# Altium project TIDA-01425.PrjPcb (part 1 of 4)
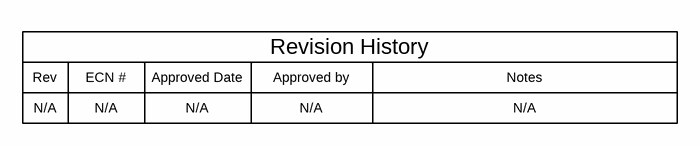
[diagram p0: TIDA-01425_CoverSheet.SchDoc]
TID: TIDA-01425; TechSupport: http://www.ti.com/support; SCH_Rev: E1; PRJ_Title: Stand-Alone Gateway with Ethernet and CAN; PRJ_Number: TIDA-01425; PRJ_Engineer2: Donovan Porter; PRJ_Engineer: Heather Lothamer; PRJ_Customer: Public Release; PCB_Rev: E1; PCB_Layout: Krypton; CopyrightYear: 2017
12 sheets, 496 parts. Net scope: global (net labels, ports and power ports of the same name join across sheets).
Board file: TIDA-01425.PcbDoc
Sheets:
  TIDA-01425_CoverSheet.SchDoc
  DCDC PWR.schdoc
  LP873x (PMIC).SchDoc
  ANA PWR.SchDoc
  DIG PWR.SchDoc
  J6Entry.SchDoc
  J6E DDR.SchDoc
  DDR3.schdoc
  Ethernet_subsystem.SchDoc
  CAN_subsystem2.0.SchDoc
  JTAG.SchDoc
  TIDA-01425_EVM_Hardware.SchDoc

## Sheet TIDA-01425_CoverSheet.SchDoc: CoverSheet
size 431 x 279 mm; Date: Not shown in title block; ApprovedBy: Not shown in title block; CheckedBy: Not shown in title block; Author: Not shown in title block; CompanyName: Not shown in title block; DrawnBy: Donovan Porter; Engineer: Not shown in title block; Organization: Not shown in title block; Address1: Not shown in title block; Address2: Not shown in title block; Address3: Not shown in title block; Address4: Not shown in title block; DocumentNumber: 1; Revision: Use project parameter SCH_Rev; SheetNumber: 1; SheetTotal: 12; PageSetup: Record=PageOptions¦CenterHorizontal=True¦CenterVertical=True¦PrintScale=1.00¦XCorrection=1.00¦YCorrection=1.00¦PrintKind=0¦BorderSize=5000000¦LeftOffset=0¦BottomOffset=0¦Orientation=2¦PaperLength=1000¦PaperWidth=1000¦Scale=100¦PaperSource=15¦PrintQuality=600¦MediaType=1¦DitherType=10¦PaperKind=Letter¦PrintScaleMode=1

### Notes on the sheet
- Rev
- N/A
- ECN #
- Approved Date
- Approved by
- Revision History
- Notes

## Sheet DCDC PWR.schdoc: LM53635-Q1
size 431 x 279 mm; Date: Not shown in title block; ApprovedBy: Not shown in title block; CheckedBy: Not shown in title block; Author: Not shown in title block; CompanyName: Not shown in title block; DrawnBy: Donovan Porter; Engineer: Not shown in title block; Organization: Not shown in title block; Address1: Not shown in title block; Address2: Not shown in title block; Address3: Not shown in title block; Address4: Not shown in title block; DocumentNumber: 7; Revision: Use project parameter SCH_Rev; SheetNumber: 7; SheetTotal: 12; PageSetup: Record=PageOptions¦CenterHorizontal=True¦CenterVertical=True¦PrintScale=1.00¦XCorrection=1.00¦YCorrection=1.00¦PrintKind=0¦BorderSize=5000000¦LeftOffset=0¦BottomOffset=0¦Orientation=2¦PaperLength=1000¦PaperWidth=1000¦Scale=100¦PaperSource=15¦PrintQuality=600¦MediaType=1¦DitherType=10¦PaperKind=Letter¦PrintScaleMode=1
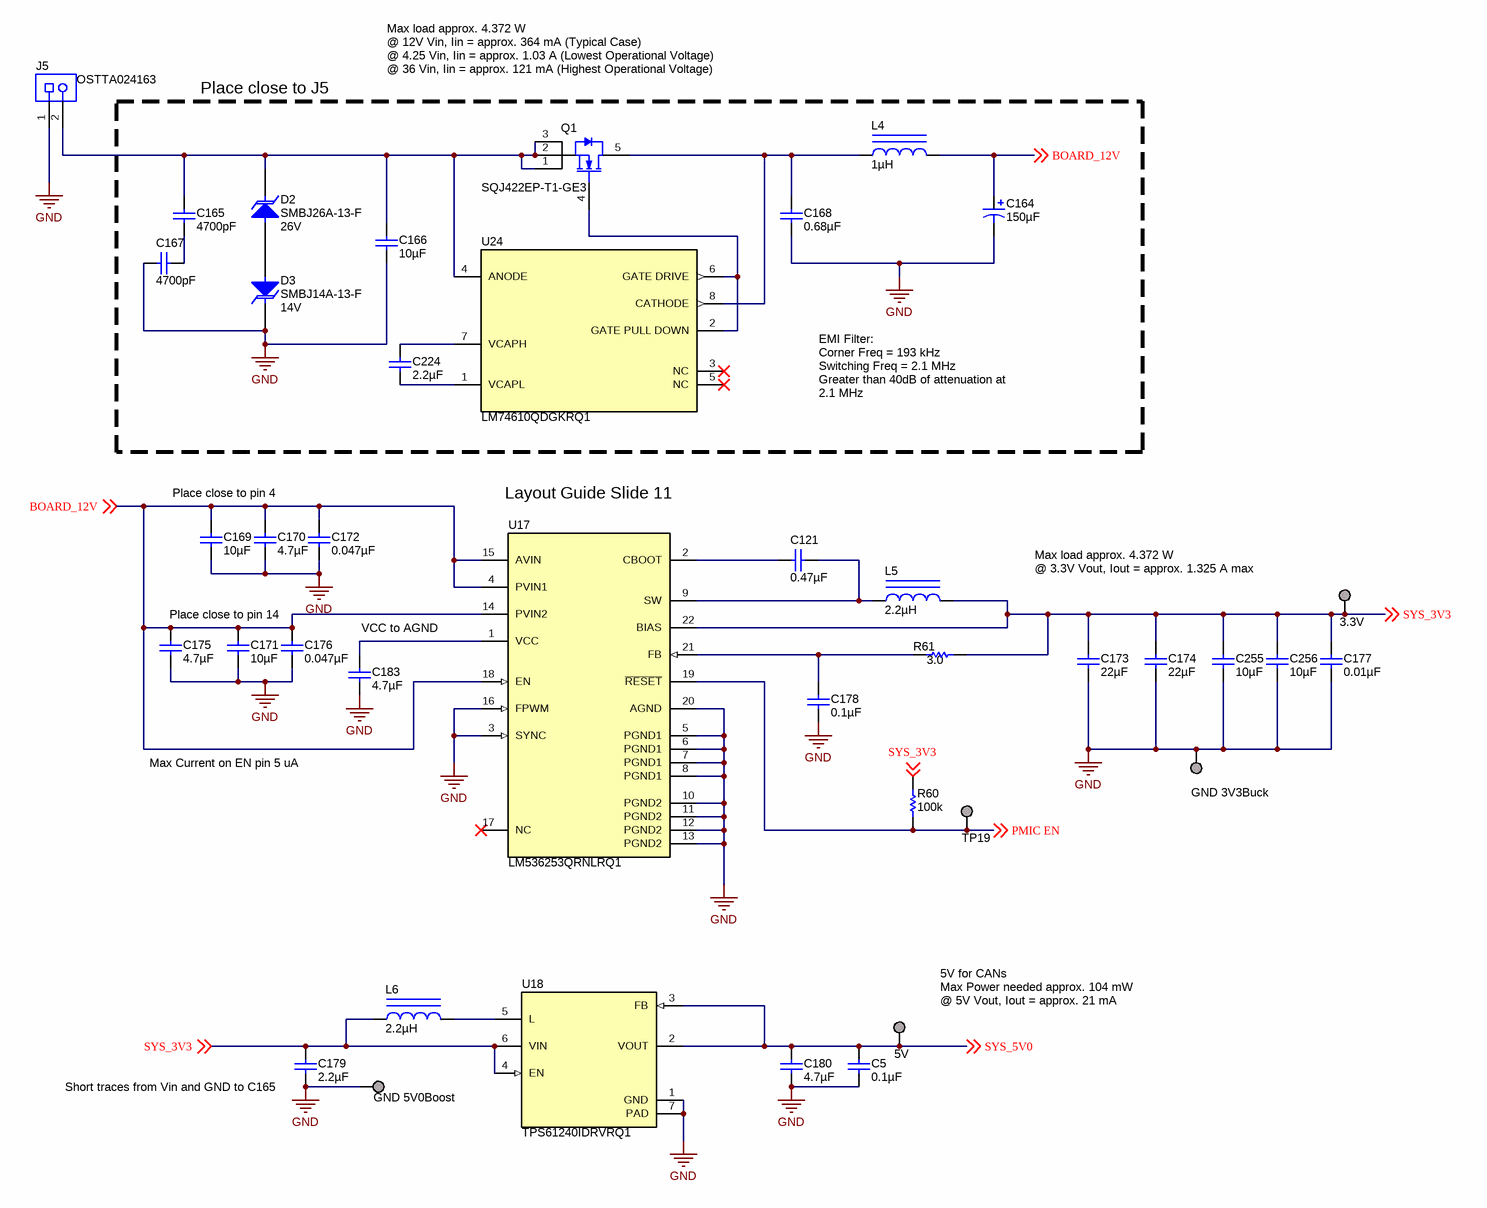
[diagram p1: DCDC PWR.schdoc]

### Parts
3.3V  PAD_1MM_SQUARE  [PAD_1MM_SQUARE]  (value not drawn)  (no BOM)
5V  PAD_1MM_SQUARE  [PAD_1MM_SQUARE]  (value not drawn)  (no BOM)
C5  ValueDisplayed: 0.1µF  [0402]  (hidden comment: GRM155R71C104JA88D)
C121  ValueDisplayed: 0.47µF  [0402]  (hidden comment: JMK105B7474KVHF)
C164  ValueDisplayed: 150µF  [SM_RADIAL_10BMM]  (hidden comment: UUD1H151MNL1GS)
C165  ValueDisplayed: 4700pF  [0402]  (hidden comment: GRM155R71H472KA01D)
C166  ValueDisplayed: 10µF  [1210_270]  (hidden comment: GRM32ER71H106KA12L)
C167  ValueDisplayed: 4700pF  [0402]  (hidden comment: GRM155R71H472KA01D)
C168  ValueDisplayed: 0.68µF  [1210_150]  (hidden comment: GRM32NR71H684KA01L)
C169  ValueDisplayed: 10µF  [1206_180]  (hidden comment: CL31B106KBHNNNE)
C170  ValueDisplayed: 4.7µF  [1206_180]  (hidden comment: C3216X7R1H475K160AC)
C171  ValueDisplayed: 10µF  [1206_180]  (hidden comment: CL31B106KBHNNNE)
C172  ValueDisplayed: 0.047µF  [0805_HV]  (hidden comment: GRM21BR71H473KA01L)
C173  ValueDisplayed: 22µF  [1210_280]  (hidden comment: C3225X7R1C226K250AC)
C174  ValueDisplayed: 22µF  [1210_280]  (hidden comment: C3225X7R1C226K250AC)
C175  ValueDisplayed: 4.7µF  [1206_180]  (hidden comment: C3216X7R1H475K160AC)
C176  ValueDisplayed: 0.047µF  [0805_HV]  (hidden comment: GRM21BR71H473KA01L)
C177  ValueDisplayed: 0.01µF  [0402_065]  (hidden comment: 520L103KT16T)
C178  ValueDisplayed: 0.1µF  [0603]  (hidden comment: C1608X7R1E104K080AA)
C179  ValueDisplayed: 2.2µF  [0603]  (hidden comment: CGA3E1X7S1C225M080AC)
C180  ValueDisplayed: 4.7µF  [1206_180]  (hidden comment: GCM31CR71C475KA37L)
C183  ValueDisplayed: 4.7µF  [1210_280]  (hidden comment: 1210ZC475KAT2A)
C224  ValueDisplayed: 2.2µF  [0805_HV]  (hidden comment: GRM21BR71C225KA12L)
C255  ValueDisplayed: 10µF  [0805_HV]  (hidden comment: EMK212BB7106MG-T)
C256  ValueDisplayed: 10µF  [0805_HV]  (hidden comment: EMK212BB7106MG-T)
D2  SMBJ26A-13-F  value 26V  [SMB]
D3  SMBJ14A-13-F  value 14V  [SMB]
GND_3V3Buck  PAD_3.2x1.9MM_SMD  [PAD_3-2x1-9MM_SMD]  (value not drawn)  (no BOM)
GND_5V0Boost  PAD_3.2x1.9MM_SMD  [PAD_3-2x1-9MM_SMD]  (value not drawn)  (no BOM)
J5  OSTTA024163  [On-Shore_OSTTA024163]
L4  ValueDisplayed: 1µH  [SRN4012TA]  (hidden comment: SRN4012TA-1R0M)
L5  ValueDisplayed: 2.2µH  [WE-TPC-XLH2]  (hidden comment: 7440650022)
L6  ValueDisplayed: 2.2µH  [B82462G4]  (hidden comment: B82462G4222M)
Q1  SQJ422EP-T1-GE3  [PowerPAK_SO-8L]
R60  ValueDisplayed: 100k  [0805_HV]  (hidden comment: RR1220P-104-D)
R61  ValueDisplayed: 3.0  [0603]  (hidden comment: CRCW06033R00JNEA)
TP19  PAD_1MM_SQUARE  [PAD_1MM_SQUARE]  (value not drawn)  (no BOM)
U17  LM536253QRNLRQ1  [RNL0022A_NV]
U18  TPS61240IDRVRQ1  [DRV0006A]
U24  LM74610QDGKRQ1  [DGK0008A_N]

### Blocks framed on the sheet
Place close to J5: C164-C168 C224 D2 D3 L4 Q1 U24

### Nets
GND: C5.2 C164.2(-) C166.2 C167.1 C168.2 C169.2 C170.2 C171.2 C172.2 C173.2 C174.2 C175.2 C176.2 C177.2 C178.2 C179.2 C180.2 C183.2 C255.2 C256.2 D3.1(K) GND_3V3Buck.1 GND_5V0Boost.1 J5.1 U17.3(SYNC) U17.5(PGND1) U17.6(PGND1) U17.7(PGND1) U17.8(PGND1) U17.10(PGND2) U17.11(PGND2) U17.12(PGND2) U17.13(PGND2) U17.16(FPWM) U17.20(AGND) U18.1(GND) U18.7(PAD)
BOARD_12V: C164.1(+) C169.1 C170.1 C171.1 C172.1 C175.1 C176.1 L4.2 U17.4(PVIN1) U17.14(PVIN2) U17.15(AVIN) U17.18(EN) ; off-sheet BOARD_12V
PMIC EN: R60.1 TP19.1 U17.19(~{RESET}) ; off-sheet PMIC EN
SYS_3V3: 3.3V.1 C173.1 C174.1 C177.1 C179.1 C255.1 C256.1 L5.2 L6.1 R60.2 R61.2 U17.22(BIAS) U18.4(EN) U18.6(VIN) ; off-sheet SYS_3V3
SYS_5V0: 5V.1 C5.1 C180.1 U18.2(VOUT) U18.3(FB) ; off-sheet SYS_5V0
NetC121_1: C121.1 L5.1 U17.9(SW)
NetC121_2: C121.2 U17.2(CBOOT)
NetC165_1: C165.1 C166.1 D2.1(K) J5.2 Q1.1(S) Q1.2(S) Q1.3(S) U24.4(ANODE)
NetC165_2: C165.2 C167.2
NetC168_1: C168.1 L4.1 Q1.5(D) U24.8(CATHODE)
NetC178_1: C178.1 R61.1 U17.21(FB)
NetC183_1: C183.1 U17.1(VCC)
NetC224_1: C224.1 U24.7(VCAPH)
NetC224_2: C224.2 U24.1(VCAPL)
NetD2_2: D2.2(A) D3.2(A)
NetL6_2: L6.2 U18.5(L)
NetQ1_4: Q1.4(G) U24.2(GATE_PULL_DOWN) U24.6(GATE_DRIVE)

Not connected (* = marked no-connect by the designer): U17 17(NC)*; U24 3(NC)* 5(NC)*

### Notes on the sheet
- Max load approx. 4.372 W
  @ 12V Vin, Iin = approx. 364 mA (Typical Case)
  @ 4.25 Vin, Iin = approx. 1.03 A (Lowest Operational Voltage)
  @ 36 Vin, Iin = approx. 121 mA (Highest Operational Voltage)
- EMI Filter:
  Corner Freq = 193 kHz
  Switching Freq = 2.1 MHz
  Greater than 40dB of attenuation at 2.1 MHz
- Place close to pin 4
- Layout Guide Slide 11
- (near 3.3V) Max load approx. 4.372 W
  @ 3.3V Vout, Iout = approx. 1.325 A max
- Place close to pin 14
- (near C183) VCC to AGND
- Max Current on EN pin 5 uA
- (near 5V) 5V for CANs
  Max Power needed approx. 104 mW
  @ 5V Vout, Iout = approx. 21 mA
- (near C179) Short traces from Vin and GND to C165

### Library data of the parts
3.3V 5V TP19 = PAD_1MM_SQUARE: 1.0x1.0mm pad, square, SMD; Manufacturer: Any
C5 = GRM155R71C104JA88D: CAP, CERM, 0.1 µF, 16 V, +/- 5%, X7R, 0402; Manufacturer: MuRata; Polarized: N; CompType: Capacitor; Value: 0.1uF; U/M: EA; Cap_F: 0.0000001; Tolerance_%: 5; Value1: Unknown; VDC_V: 16; Value2: 16V; TaMin_C: -55; TaMax_C: 125; SizeArea_mm2: 0.5; SizeAreaWB_mm2: 3; SizeX_mm: 1; SizeZ_mm: 0.6; AEC Category: Q200
C121 = JMK105B7474KVHF: CAP, CERM, 0.47 µF, 6.3 V, +/- 10%, X7R, 0402; Manufacturer: Taiyo Yuden; Polarized: N; CompType: Capacitor; Value: 0.47uF; U/M: EA; Cap_F: 0.00000047; Tolerance_%: 10; Value1: Unknown; VDC_V: 6.3; Value2: 6.3V; TaMin_C: -55; TaMax_C: 125; SizeArea_mm2: 0.5; SizeAreaWB_mm2: 3; SizeX_mm: 1; SizeZ_mm: 0.6; AEC Category: Q200
C164 = UUD1H151MNL1GS: CAP, AL, 150 µF, 50 V, +/- 20%, 0.18 ohm, SMD; Manufacturer: Nichicon; Polarized: Y; CompType: Capacitor; Value: 150uF; U/M: EA; Cap_F: 0.00015; Tolerance_%: 20; VDC_V: 50; Value2: 50V; ESR_ohm: 0.18; IRMS_A: 0.67; TaMin_C: -55; TaMax_C: 105; Cap_Case: 10x10; SizeAreaWB_mm2: 159.9; SizeArea_mm2: 113.3; SizeX_mm: 11; SizeY_mm: 10.3; SizeZ_mm: 10.2; AEC Category: Q200
C165 C167 = GRM155R71H472KA01D: CAP, CERM, 4700 pF, 50 V, +/- 10%, X7R, 0402; Manufacturer: MuRata; Polarized: N; CompType: Capacitor; Value: 4700pF; U/M: EA; Cap_F: 0.0000000047; Tolerance_%: 10; Value1: Unknown; VDC_V: 50; Value2: 50V; TaMin_C: -55; TaMax_C: 125; SizeArea_mm2: 0.5; SizeAreaWB_mm2: 3; SizeX_mm: 1; SizeZ_mm: 0.6; AEC Category: Q200
C166 = GRM32ER71H106KA12L: CAP, CERM, 10 µF, 50 V, +/- 10%, X7R, 1210; Manufacturer: MuRata; Polarized: N; CompType: Capacitor; Value: 10uF; U/M: EA; Cap_F: 0.00001; Tolerance_%: 10; Value1: Unknown; VDC_V: 50; Value2: 50V; TaMin_C: -55; TaMax_C: 125; Cap_Case: 1210; SizeArea_mm2: 8; SizeAreaWB_mm2: 14.7; SizeX_mm: 3.2; SizeY_mm: 2.5; SizeZ_mm: 2.7; AEC Category: Q200
C168 = GRM32NR71H684KA01L: CAP, CERM, 0.68 µF, 50 V, +/- 10%, X7R, 1210; Manufacturer: MuRata; Polarized: N; CompType: Capacitor; Value: 0.68uF; U/M: EA; Cap_F: 0.00000068; Tolerance_%: 10; Value1: Unknown; VDC_V: 50; Value2: 50V; TaMin_C: -55; TaMax_C: 125; Cap_Case: 1210; SizeArea_mm2: 8; SizeAreaWB_mm2: 14.7; SizeX_mm: 3.2; SizeY_mm: 2.5; SizeZ_mm: 1.5; AEC Category: Q200
C169 C171 = CL31B106KBHNNNE: CAP, CERM, 10 µF, 50 V, +/- 10%, X7R, 1206; Manufacturer: Samsung; Polarized: N; CompType: Capacitor; Value: 10uF; U/M: EA; Cap_F: 0.00001; Tolerance_%: 10; Value1: Unknown; VDC_V: 50; Value2: 50V; TaMin_C: -55; TaMax_C: 125; Cap_Case: 1206; SizeArea_mm2: 5.12; SizeAreaWB_mm2: 10.92; SizeX_mm: 3.2; SizeY_mm: 1.6; SizeZ_mm: 1.8; AEC Category: Q200
C170 C175 = C3216X7R1H475K160AC: CAP, CERM, 4.7 µF, 50 V, +/- 10%, X7R, 1206; Manufacturer: TDK; Polarized: N; CompType: Capacitor; Value: 4.7uF; U/M: EA; Cap_F: 0.0000047; Tolerance_%: 10; ESR_ohm: 0.003158; Value1: 0.003158 ohm; VDC_V: 50; Value2: 50V; IRMS_A: 4.08379; TaMin_C: -55; TaMax_C: 125; SizeArea_mm2: 5.12; SizeAreaWB_mm2: 10.92; SizeX_mm: 3.2; SizeY_mm: 1.6; SizeZ_mm: 1.8; AEC Category: Q200
C172 C176 = GRM21BR71H473KA01L: CAP, CERM, 0.047 µF, 50 V, +/- 10%, X7R, 0805; Manufacturer: MuRata; Polarized: N; CompType: Capacitor; Value: 0.047uF; U/M: EA; Cap_F: 0.000000047; Tolerance_%: 10; Value1: Unknown; VDC_V: 50; Value2: 50V; TaMin_C: -55; TaMax_C: 125; Cap_Case: 0805; SizeArea_mm2: 2.5; SizeAreaWB_mm2: 6.75; SizeX_mm: 2; SizeY_mm: 1.25; SizeZ_mm: 1.45; AEC Category: Q200
C173 C174 = C3225X7R1C226K250AC: CAP, CERM, 22 µF, 16 V, +/- 10%, X7R, 1210; Manufacturer: TDK; Polarized: N; CompType: Capacitor; Value: 22uF; U/M: EA; Cap_F: 0.000022; Tolerance_%: 10; ESR_ohm: 0.002582; Value1: 0.002582 ohm; VDC_V: 16; Value2: 16V; IRMS_A: 4.57562; TaMin_C: -55; TaMax_C: 125; SizeArea_mm2: 8; SizeAreaWB_mm2: 14.7; SizeX_mm: 3.2; SizeY_mm: 2.5; SizeZ_mm: 2.8; AEC Category: Q200
C177 = 520L103KT16T: CAP, CERM, 0.01 µF, 16 V, +/- 10%, X7R, 0402; Manufacturer: AT Ceramics; Polarized: N; CompType: Capacitor; Value: 0.01uF; U/M: EA; Cap_F: 0.00000001; Tolerance_%: 10; Value1: Unknown; VDC_V: 16; Value2: 16V; TaMin_C: -55; TaMax_C: 125; Cap_Case: 0402; SizeArea_mm2: 0.5; SizeAreaWB_mm2: 3; SizeX_mm: 1; SizeZ_mm: 0.65; AEC Category: Q200
C178 = C1608X7R1E104K080AA: CAP, CERM, 0.1 µF, 25 V, +/- 10%, X7R, 0603; Manufacturer: TDK; Polarized: N; CompType: Capacitor; Value: 0.1uF; U/M: EA; Cap_F: 0.0000001; Tolerance_%: 10; Value1: Unknown; VDC_V: 25; Value2: 25V; TaMin_C: -55; TaMax_C: 125; SizeArea_mm2: 1.28; SizeAreaWB_mm2: 4.68; SizeX_mm: 1.6; SizeY_mm: 0.8; SizeZ_mm: 1; AEC Category: Q200
C179 = CGA3E1X7S1C225M080AC: CAP, CERM, 2.2 µF, 16 V, +/- 20%, X7S, AEC-Q200 Grade 1, 0603; Manufacturer: TDK; Polarized: N; CompType: Capacitor; Value: 2.2uF; U/M: EA; Cap_F: 0.0000022; Tolerance_%: 20; Value1: Unknown; VDC_V: 16; Value2: 16V; TaMin_C: -55; TaMax_C: 125; SizeArea_mm2: 1.28; SizeAreaWB_mm2: 4.68; SizeX_mm: 1.6; SizeY_mm: 0.8; SizeZ_mm: 1; AEC Category: Q200; AEC Qualified: Y
C180 = GCM31CR71C475KA37L: CAP, CERM, 4.7 µF, 16 V, +/- 10%, X7R, AEC-Q200 Grade 1, 1206; Manufacturer: MuRata; Polarized: N; CompType: Capacitor; Value: 4.7uF; U/M: EA; Cap_F: 0.0000047; Tolerance_%: 10; Value1: Unknown; VDC_V: 16; Value2: 16V; TaMin_C: -55; TaMax_C: 125; Cap_Case: 1206; SizeArea_mm2: 5.12; SizeAreaWB_mm2: 10.92; SizeX_mm: 3.2; SizeY_mm: 1.6; SizeZ_mm: 1.8; AEC Category: Q200; AEC Qualified: Y; AEC Grade: 1
C183 = 1210ZC475KAT2A: CAP, CERM, 4.7 µF, 10 V, +/- 10%, X7R, 1210; Manufacturer: AVX; Polarized: N; CompType: Capacitor; Value: 4.7uF; U/M: EA; Cap_F: 0.0000047; Tolerance_%: 10; Value1: Unknown; Value2: 10V; TaMin_C: -55; TaMax_C: 125; Cap_Case: 1210; SizeArea_mm2: 8; SizeAreaWB_mm2: 14.7; SizeX_mm: 3.2; SizeY_mm: 2.5; SizeZ_mm: 2.8; AEC Category: Q200
C224 = GRM21BR71C225KA12L: CAP, CERM, 2.2 µF, 16 V, +/- 10%, X7R, 0805; Manufacturer: MuRata; Polarized: N; CompType: Capacitor; Value: 2.2uF; U/M: EA; Cap_F: 0.0000022; Tolerance_%: 10; ESR_ohm: 0.004; Value1: 0.004 ohm; VDC_V: 16; Value2: 16V; TaMin_C: -55; TaMax_C: 125; Cap_Case: 0805; SizeArea_mm2: 2.5; SizeAreaWB_mm2: 6.75; SizeX_mm: 2; SizeY_mm: 1.25; SizeZ_mm: 1.45; AEC Category: Q200
C255 C256 = EMK212BB7106MG-T: CAP, CERM, 10 µF, 16 V, +/- 20%, X7R, 0805; Manufacturer: Taiyo Yuden; Polarized: N; CompType: Capacitor; Value: 10uF; U/M: EA; Cap_F: 0.00001; Tolerance_%: 20; Value1: Unknown; VDC_V: 16; Value2: 16V; TaMin_C: -55; TaMax_C: 125; Cap_Case: 0805; SizeArea_mm2: 2.5; SizeAreaWB_mm2: 6.75; SizeX_mm: 2; SizeY_mm: 1.25; SizeZ_mm: 1.45; AEC Category: Q200
D2 = SMBJ26A-13-F: Diode, TVS, Uni, 26 V, 42.1 Vc, SMB; Manufacturer: Diodes Inc.; U/M: EA; Power_W: 5; Vr_V: 26; Value1: 5W; SizeAreaWB_mm2: 44.156; SizeArea_mm2: 21.336; SizeX_mm: 5.6; SizeY_mm: 3.81; SizeZ_mm: 2.6; AEC Category: Q101
D3 = SMBJ14A-13-F: Diode, TVS, Uni, 14 V, 23.2 Vc, SMB; Manufacturer: Diodes Inc.; U/M: EA; Power_W: 5; Vr_V: 14; Value1: 5W; SizeAreaWB_mm2: 44.156; SizeArea_mm2: 21.336; SizeX_mm: 5.6; SizeY_mm: 3.81; SizeZ_mm: 2.6; AEC Category: Q101
GND_3V3Buck GND_5V0Boost = PAD_3.2x1.9MM_SMD: 3.2x1.9mm Pad, SMD; Manufacturer: Any
J5 = OSTTA024163: Terminal Block, 2x1, 5.08mm, TH; Manufacturer: On-Shore Technology; SymbolCreator: a0412235
L4 = SRN4012TA-1R0M: Inductor, Shielded, Ferrite, 1 µH, 2.2 A, 0.0504 ohm, AEC-Q200 Grade 1, SMD; Manufacturer: Bourns; Value: 1uH; Ind_H: 1.0E-6; Imax_A: 2.2; Irms: 2.2A @ 40C rise; Isat: 2.8A @ 30% inductance drop; DCR_ohm: 0.0504; Value2: 2.2A; SizeAreaWB_mm2: 25; SizeArea_mm2: 16; SizeX_mm: 4; SizeZ_mm: 1.2; AEC Category: Q200; AEC Qualified: Y; AEC Grade: 1
L5 = 7440650022: Inductor, Shielded Drum Core, Ferrite, 2.2 µH, 5.9 A, 0.0104 ohm, SMD; Manufacturer: Wurth Elektronik; Value: 2.2uH; Ind_H: 2.2E-6; Imax_A: 5.9; Irms: 6.2A @ 30C rise; Isat: 5.9A @ 35% inductance drop; DCR_ohm: 0.0104; Value2: 5.9A; SizeAreaWB_mm2: 144; SizeArea_mm2: 100; SizeX_mm: 10; SizeZ_mm: 2.8; AEC Category: Q200
L6 = B82462G4222M: Inductor, Shielded Drum Core, Ferrite, 2.2 µH, 2.55 A, 0.025 ohm, AEC-Q200 Grade 0, SMD; Manufacturer: TDK; Value: 2.2uH; Ind_H: 2.2E-6; Imax_A: 2.55; Irms: 2.55A @ 40C rise; Isat: 2.6A @ 10% inductance drop; DCR_ohm: 0.025; Value2: 2.55A; AEC Category: Q200; AEC Qualified: Y; AEC Grade: 0
Q1 = SQJ422EP-T1-GE3: MOSFET, N-CH, 40 V, 75 A, PowerPAK_SO-8L; Manufacturer: Vishay-Siliconix; Alternate Manufacturer: None; SymbolCreator: a0412235; U/M: EA; ChType: N; Value: 40V; VdsMax_V: 40; Value1: 0.0043 ohm; Rdson45_ohm: 0.0043; Value2: 67 nC; QgTyp_nC: 67; Vgs_V: 20; IdsMax_A: 75; SizeAreaWB_mm2: 58.1095; SizeArea_mm2: 31.5495; SizeX_mm: 6.15; SizeY_mm: 5.13; SizeZ_mm: 1.14; AEC Category: Q101
R60 = RR1220P-104-D: RES, 100 k, 0.5%, 0.1 W, 0805; Manufacturer: Susumu Co Ltd; CompType: Resistor; Value: 100k; Res_ohm: 100000; Tolerance_%: 0.5; Power_W: 0.1; Value2: 0.1W; VDC_V: 100; TempCo: 25 ppm/C; SizeArea_mm2: 2.5; SizeX_mm: 2; SizeY_mm: 1.25; SizeZ_mm: 1.45; EIA_Code: E192; U/M: EA; AEC Category: Q200
R61 = CRCW06033R00JNEA: RES, 3.0, 5%, 0.1 W, 0603; Manufacturer: Vishay-Dale; CompType: Resistor; Value: 3.0; Res_ohm: 3; Value_Code: 3R00; Tolerance_%: 5; Power_W: 0.1; Value2: 0.1W; VDC_V: 75; TempCo: 200 ppm/C; EIA_Code: E24; U/M: EA; AEC Category: Q200
U17 = LM536253QRNLRQ1: 2.5/3.5A, 36 V Synchronous, 2.1MHz, Automotive Step Down DC-DC Converter, RNL0022A (VQFN-HR-22); Alternate PartNumber: LM536253QRNLTQ1; Manufacturer: Texas Instruments; SymbolCreator: Altium; SizeArea_mm2: 20; SizeAreaWB_mm2: 42; SizeX_mm: 4; SizeY_mm: 5; SizeZ_mm: 0.9; CompType: IC; U/M: EA
U18 = TPS61240IDRVRQ1: Automotive Catalog 5V, 400mA, 4MHz Step-Up DC/DC Converter, DRV0006A; Manufacturer: Texas Instruments; SymbolCreator: a799628; SizeArea_mm2: 4; SizeAreaWB_mm2: 9; SizeX_mm: 2; SizeZ_mm: 0.8; CompType: IC; U/M: EA
U24 = LM74610QDGKRQ1: Zero Iq Reverse Polarity Protection Smart Diode Controller, DGK0008A (VSSOP-8); Manufacturer: Texas Instruments; SymbolCreator: Altium; SizeArea_mm2: 15.655; SizeAreaWB_mm2: 35.955; SizeX_mm: 5.05; SizeY_mm: 3.1; SizeZ_mm: 1.1; CompType: IC; U/M: EA

## Sheet LP873x (PMIC).SchDoc: PMIC
size 431 x 279 mm; Date: Not shown in title block; ApprovedBy: Not shown in title block; CheckedBy: Not shown in title block; Author: Not shown in title block; CompanyName: Not shown in title block; DrawnBy: Donovan Porter; Engineer: Not shown in title block; Organization: Not shown in title block; Address1: Not shown in title block; Address2: Not shown in title block; Address3: Not shown in title block; Address4: Not shown in title block; DocumentNumber: 2; Revision: Use project parameter SCH_Rev; SheetNumber: 2; SheetTotal: 12; PageSetup: Record=PageOptions¦CenterHorizontal=True¦CenterVertical=True¦PrintScale=1.00¦XCorrection=1.00¦YCorrection=1.00¦PrintKind=0¦BorderSize=5000000¦LeftOffset=0¦BottomOffset=0¦Orientation=2¦PaperLength=1000¦PaperWidth=1000¦Scale=100¦PaperSource=15¦PrintQuality=600¦MediaType=1¦DitherType=10¦PaperKind=Letter¦PrintScaleMode=1
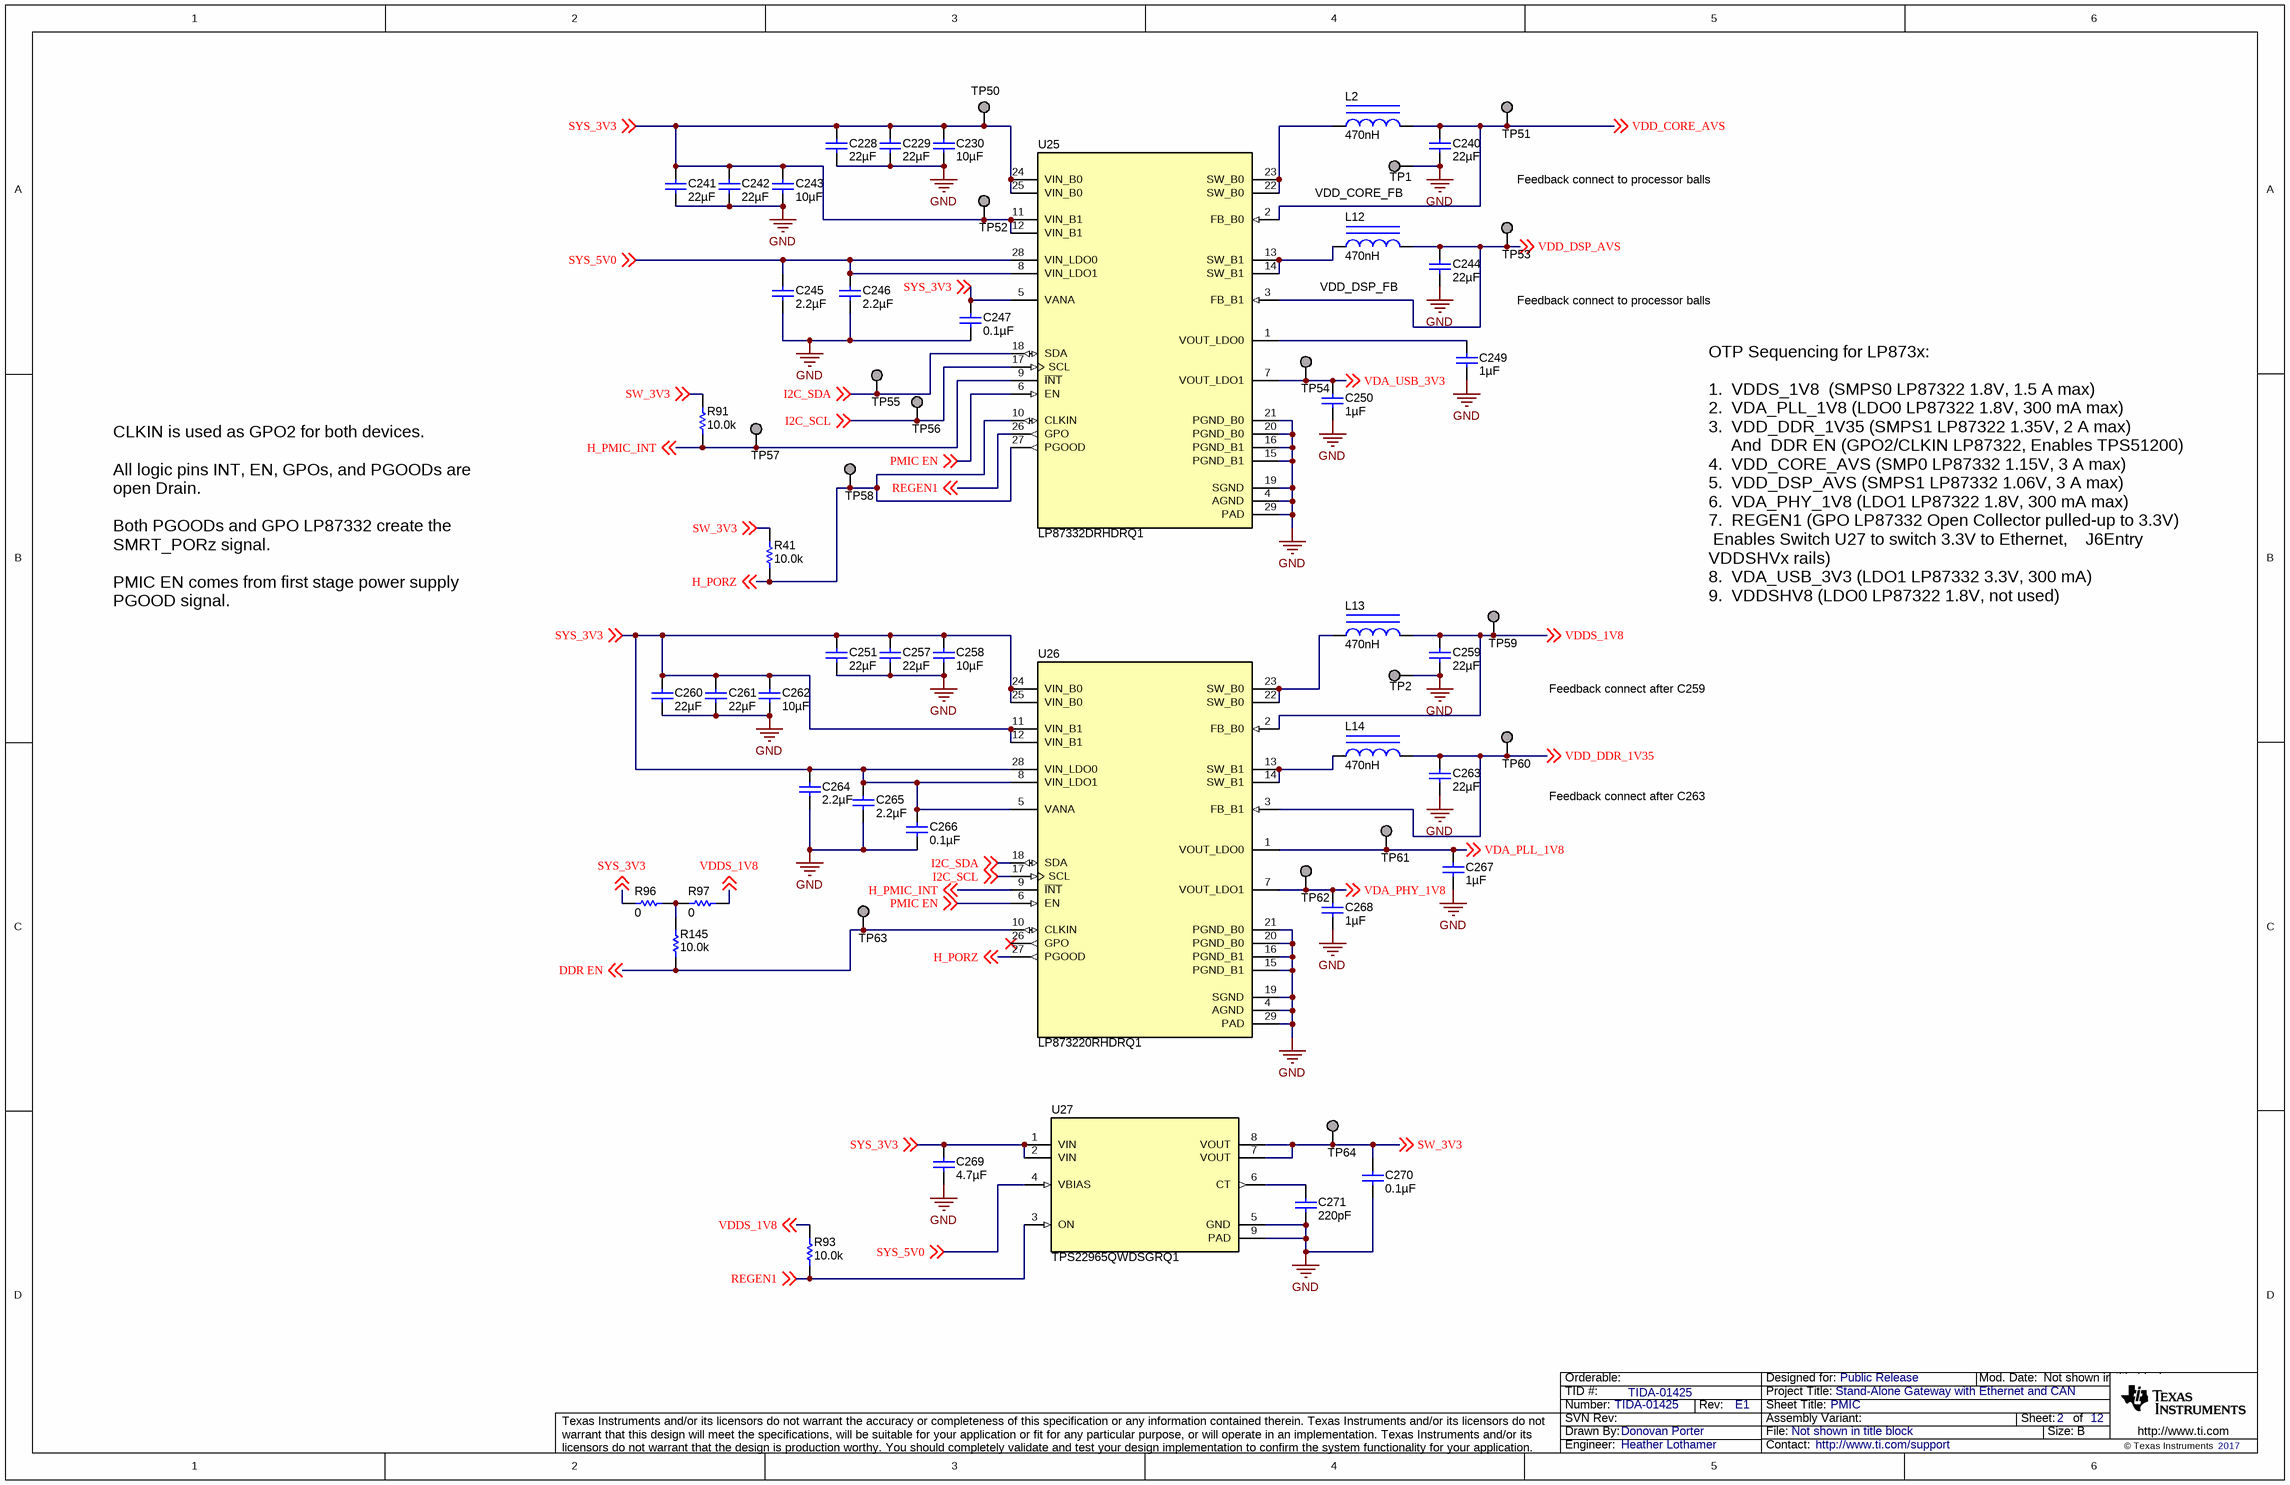
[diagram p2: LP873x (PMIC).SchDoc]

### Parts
C228  ValueDisplayed: 22µF  [1210_270L]  (hidden comment: GRM32ER71C226KE18L)
C229  ValueDisplayed: 22µF  [1210_270L]  (hidden comment: GRM32ER71C226KE18L)
C230  ValueDisplayed: 10µF  [0805L]  (hidden comment: GCM21BR71A106KE22L)
C240  ValueDisplayed: 22µF  [1206_180L]  (hidden comment: GCM31CR71A226KE02)
C241  ValueDisplayed: 22µF  [1210_270L]  (hidden comment: GRM32ER71C226KE18L)
C242  ValueDisplayed: 22µF  [1210_270L]  (hidden comment: GRM32ER71C226KE18L)
C243  ValueDisplayed: 10µF  [0805L]  (hidden comment: GCM21BR71A106KE22L)
C244  ValueDisplayed: 22µF  [1206_180L]  (hidden comment: GCM31CR71A226KE02)
C245  ValueDisplayed: 2.2µF  [0603L]  (hidden comment: GRM188R71A225KE15D)
C246  ValueDisplayed: 2.2µF  [0603L]  (hidden comment: GRM188R71A225KE15D)
C247  ValueDisplayed: 0.1µF  [0402L]  (hidden comment: C1005X7R1E104M050BB)
C249  ValueDisplayed: 1µF  [0603L]  (hidden comment: GCM188R71C105KA64D)
C250  ValueDisplayed: 1µF  [0603L]  (hidden comment: GCM188R71C105KA64D)
C251  ValueDisplayed: 22µF  [1210_270L]  (hidden comment: GRM32ER71C226KE18L)
C257  ValueDisplayed: 22µF  [1210_270L]  (hidden comment: GRM32ER71C226KE18L)
C258  ValueDisplayed: 10µF  [0805L]  (hidden comment: GCM21BR71A106KE22L)
C259  ValueDisplayed: 22µF  [1206_180L]  (hidden comment: GCM31CR71A226KE02)
C260  ValueDisplayed: 22µF  [1210_270L]  (hidden comment: GRM32ER71C226KE18L)
C261  ValueDisplayed: 22µF  [1210_270L]  (hidden comment: GRM32ER71C226KE18L)
C262  ValueDisplayed: 10µF  [0805L]  (hidden comment: GCM21BR71A106KE22L)
C263  ValueDisplayed: 22µF  [1206_180L]  (hidden comment: GCM31CR71A226KE02)
C264  ValueDisplayed: 2.2µF  [0603L]  (hidden comment: GRM188R71A225KE15D)
C265  ValueDisplayed: 2.2µF  [0603L]  (hidden comment: GRM188R71A225KE15D)
C266  ValueDisplayed: 0.1µF  [0402L]  (hidden comment: C1005X7R1E104M050BB)
C267  ValueDisplayed: 1µF  [0603L]  (hidden comment: GCM188R71C105KA64D)
C268  ValueDisplayed: 1µF  [0603L]  (hidden comment: GCM188R71C105KA64D)
C269  ValueDisplayed: 4.7µF  [0805_HV]  (hidden comment: GCM21BR71C475KA73L)
C270  ValueDisplayed: 0.1µF  [0402]  (hidden comment: C0402C104K4RACAUTO)
C271  ValueDisplayed: 220pF  [0603]  (hidden comment: 06035A221FAT2A)
L2  ValueDisplayed: 470nH  [DFE252012P]  (hidden comment: DFE252012PD-R47M)
L12  ValueDisplayed: 470nH  [DFE252012P]  (hidden comment: DFE252012PD-R47M)
L13  ValueDisplayed: 470nH  [DFE252012P]  (hidden comment: DFE252012PD-R47M)
L14  ValueDisplayed: 470nH  [DFE252012P]  (hidden comment: DFE252012PD-R47M)
R41  ValueDisplayed: 10.0k  [0402L]  (hidden comment: MCR01MRTF1002)
R91  ValueDisplayed: 10.0k  [0402L]  (hidden comment: MCR01MRTF1002)
R93  ValueDisplayed: 10.0k  [0402]  (hidden comment: MCR01MRTF1002)
R96  ValueDisplayed: 0  [0402]  (hidden comment: CRCW04020000Z0ED)
R97  ValueDisplayed: 0  [0402]  (hidden comment: CRCW04020000Z0ED)
R145  ValueDisplayed: 10.0k  [0402L]  (hidden comment: MCR01MRTF1002)
TP1  PAD_1MM_SQUARE  [PAD_1MM_SQUARE]  (value not drawn)  (no BOM)
TP2  PAD_1MM_SQUARE  [PAD_1MM_SQUARE]  (value not drawn)  (no BOM)
TP50  PAD_1MM_SQUARE  [PAD_1MM_SQUARE]  (value not drawn)  (no BOM)
TP51  PAD_1MM_SQUARE  [PAD_1MM_SQUARE]  (value not drawn)  (no BOM)
TP52  PAD_1MM_SQUARE  [PAD_1MM_SQUARE]  (value not drawn)  (no BOM)
TP53  PAD_1MM_SQUARE  [PAD_1MM_SQUARE]  (value not drawn)  (no BOM)
TP54  PAD_1MM_SQUARE  [PAD_1MM_SQUARE]  (value not drawn)  (no BOM)
TP55  PAD_1MM_SQUARE  [PAD_1MM_SQUARE]  (value not drawn)  (no BOM)
TP56  PAD_1MM_SQUARE  [PAD_1MM_SQUARE]  (value not drawn)  (no BOM)
TP57  PAD_1MM_SQUARE  [PAD_1MM_SQUARE]  (value not drawn)  (no BOM)
TP58  PAD_1MM_SQUARE  [PAD_1MM_SQUARE]  (value not drawn)  (no BOM)
TP59  PAD_1MM_SQUARE  [PAD_1MM_SQUARE]  (value not drawn)  (no BOM)
TP60  PAD_1MM_SQUARE  [PAD_1MM_SQUARE]  (value not drawn)  (no BOM)
TP61  PAD_1MM_SQUARE  [PAD_1MM_SQUARE]  (value not drawn)  (no BOM)
TP62  PAD_1MM_SQUARE  [PAD_1MM_SQUARE]  (value not drawn)  (no BOM)
TP63  PAD_1MM_SQUARE  [PAD_1MM_SQUARE]  (value not drawn)  (no BOM)
TP64  TESTPOINT  [PAD_1MM_SQUARE]  (value not drawn)  (no BOM)
U25  LP87332DRHDRQ1  [RHD0028W]
U26  LP873220RHDRQ1  [RHD0028W]
U27  TPS22965QWDSGRQ1  [DSG0008B]

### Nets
GND: C228.2 C229.2 C230.2 C240.2 C241.2 C242.2 C243.2 C244.2 C245.2 C246.2 C247.2 C249.2 C250.2 C251.2 C257.2 C258.2 C259.2 C260.2 C261.2 C262.2 C263.2 C264.2 C265.2 C266.2 C267.2 C268.2 C269.2 C270.2 C271.2 TP1.1 TP2.1 U25.4(AGND) U25.15(PGND_B1) U25.16(PGND_B1) U25.19(SGND) U25.20(PGND_B0) U25.21(PGND_B0) U25.29(PAD) U26.4(AGND) U26.15(PGND_B1) U26.16(PGND_B1) U26.19(SGND) U26.20(PGND_B0) U26.21(PGND_B0) U26.29(PAD) U27.5(GND) U27.9(PAD)
VDDS_1V8: C259.1 L13.2 R93.2 R97.2 TP59.1 U26.2(FB_B0) ; off-sheet VDDS_1V8
DDR EN: R145.1 TP63.1 U26.10(CLKIN) ; off-sheet DDR EN
H_PMIC_INT: R91.1 TP57.1 U25.9(~{INT}) U26.9(~{INT}) ; off-sheet H_PMIC_INT
H_PORZ: R41.1 TP58.1 U25.10(CLKIN) U25.27(PGOOD) U26.27(PGOOD) ; off-sheet H_PORZ
I2C_SCL: TP56.1 U25.17(SCL) U26.17(SCL) ; off-sheet I2C_SCL
I2C_SDA: TP55.1 U25.18(SDA) U26.18(SDA) ; off-sheet I2C_SDA
PMIC EN: U25.6(EN) U26.6(EN) ; off-sheet PMIC EN
REGEN1: R93.1 U25.26(GPO) U27.3(ON) ; off-sheet REGEN1
SW_3V3: C270.1 R41.2 R91.2 TP64.1 U27.7(VOUT) U27.8(VOUT) ; off-sheet SW_3V3
SYS_3V3: C228.1 C229.1 C230.1 C241.1 C242.1 C243.1 C247.1 C251.1 C257.1 C258.1 C260.1 C261.1 C262.1 C264.1 C265.1 C266.1 C269.1 R96.1 TP50.1 TP52.1 U25.5(VANA) U25.11(VIN_B1) U25.12(VIN_B1) U25.24(VIN_B0) U25.25(VIN_B0) U26.5(VANA) U26.8(VIN_LDO1) U26.11(VIN_B1) U26.12(VIN_B1) U26.24(VIN_B0) U26.25(VIN_B0) U26.28(VIN_LDO0) U27.1(VIN) U27.2(VIN) ; off-sheet SYS_3V3
SYS_5V0: C245.1 C246.1 U25.8(VIN_LDO1) U25.28(VIN_LDO0) U27.4(VBIAS) ; off-sheet SYS_5V0
VDA_PHY_1V8: C268.1 TP62.1 U26.7(VOUT_LDO1) ; off-sheet VDA_PHY_1V8
VDA_PLL_1V8: C267.1 TP61.1 U26.1(VOUT_LDO0) ; off-sheet VDA_PLL_1V8
VDA_USB_3V3: C250.1 TP54.1 U25.7(VOUT_LDO1) ; off-sheet VDA_USB_3V3
VDD_CORE_AVS: C240.1 L2.2 TP51.1 U25.2(FB_B0) ; off-sheet VDD_CORE_AVS
VDD_DDR_1V35: C263.1 L14.2 TP60.1 U26.3(FB_B1) ; off-sheet VDD_DDR_1V35
VDD_DSP_AVS: C244.1 L12.2 TP53.1 U25.3(FB_B1) ; off-sheet VDD_DSP_AVS
NetC249_1: C249.1 U25.1(VOUT_LDO0)
NetC271_1: C271.1 U27.6(CT)
NetL2_1: L2.1 U25.22(SW_B0) U25.23(SW_B0)
NetL12_1: L12.1 U25.13(SW_B1) U25.14(SW_B1)
NetL13_1: L13.1 U26.22(SW_B0) U26.23(SW_B0)
NetL14_1: L14.1 U26.13(SW_B1) U26.14(SW_B1)
NetR96_2: R96.2 R97.1 R145.2

Not connected (* = marked no-connect by the designer): U26 26(GPO)*

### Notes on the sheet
- (near TP1) VDD_CORE_FB
- Feedback connect to processor balls
- VDD_DSP_FB
- CLKIN is used as GPO2 for both devices.
  All logic pins INT, EN, GPOs, and PGOODs are open Drain.
  Both PGOODs and GPO LP87332 create the SMRT_PORz signal.
  PMIC EN comes from first stage power supply PGOOD signal.
- OTP Sequencing for LP873x:
  1.  VDDS_1V8  (SMPS0 LP87322 1.8V, 1.5 A max)
  2.  VDA_PLL_1V8 (LDO0 LP87322 1.8V, 300 mA max)
  3.  VDD_DDR_1V35 (SMPS1 LP87322 1.35V, 2 A max)
  And  DDR EN (GPO2/CLKIN LP87322, Enables TPS51200)
  4.  VDD_CORE_AVS (SMP0 LP87332 1.15V, 3 A max)
  5.  VDD_DSP_AVS (SMPS1 LP87332 1.06V, 3 A max)
  6.  VDA_PHY_1V8 (LDO1 LP87322 1.8V, 300 mA max)
  7.  REGEN1 (GPO LP87332 Open Collector pulled-up to 3.3V)
  Enables Switch U27 to switch 3.3V to Ethernet, 			J6Entry VDDSHVx rails)
  8.  VDA_USB_3V3 (LDO1 LP87332 3.3V, 300 mA)
  9.  VDDSHV8 (LDO0 LP87322 1.8V, not used)
- Feedback connect after C259
- Feedback connect after C263

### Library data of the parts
C228 C229 C241 C242 C251 C257 C260 C261 = GRM32ER71C226KE18L: CAP, CERM, 22 µF, 16 V, +/- 10%, X7R, 1210; Manufacturer: MuRata; Polarized: N; CompType: Capacitor; Value: 22uF; U/M: EA; Cap_F: 0.000022; Tolerance_%: 10; ESR_ohm: 0.003; Value1: 0.003 ohm; VDC_V: 16; Value2: 16V; TaMin_C: -55; TaMax_C: 125; Cap_Case: 1210; SizeArea_mm2: 8; SizeAreaWB_mm2: 14.7; SizeX_mm: 3.2; SizeY_mm: 2.5; SizeZ_mm: 2.7; AEC Category: Q200
C230 C243 C258 C262 = GCM21BR71A106KE22L: CAP, CERM, 10 µF, 10 V, +/- 10%, X7R, 0805; Manufacturer: MuRata; Polarized: N; CompType: Capacitor; Value: 10uF; U/M: EA; Cap_F: 0.00001; Tolerance_%: 10; Value1: Unknown; Value2: 10V; TaMin_C: -55; TaMax_C: 125; Cap_Case: 0805; SizeArea_mm2: 2.5; SizeAreaWB_mm2: 6.75; SizeX_mm: 2; SizeY_mm: 1.25; SizeZ_mm: 1.45; AEC Category: Q200
C240 C244 C259 C263 = GCM31CR71A226KE02: CAP, CERM, 22 µF, 10 V, +/- 10%, X7R, AEC-Q200 Grade 1, 1206; Manufacturer: MuRata; Polarized: N; CompType: Capacitor; Value: 22uF; U/M: EA; Cap_F: 0.000022; Tolerance_%: 10; Value1: Unknown; Value2: 10V; TaMin_C: -55; TaMax_C: 125; Cap_Case: 1206; SizeArea_mm2: 5.12; SizeAreaWB_mm2: 10.92; SizeX_mm: 3.2; SizeY_mm: 1.6; SizeZ_mm: 1.8; AEC Category: Q200; AEC Qualified: Y; AEC Grade: 1
C245 C246 C264 C265 = GRM188R71A225KE15D: CAP, CERM, 2.2 µF, 10 V, +/- 10%, X7R, 0603; Manufacturer: MuRata; Polarized: N; CompType: Capacitor; Value: 2.2uF; U/M: EA; Cap_F: 0.0000022; Tolerance_%: 10; ESR_ohm: 0.009; Value1: 0.009 ohm; Value2: 10V; TaMin_C: -55; TaMax_C: 125; Cap_Case: 0603; SizeArea_mm2: 1.28; SizeAreaWB_mm2: 4.68; SizeX_mm: 1.6; SizeY_mm: 0.8; SizeZ_mm: 1; AEC Category: Q200
C247 C266 = C1005X7R1E104M050BB: CAP, CERM, 0.1 µF, 25 V, +/- 20%, X7R, 0402; Manufacturer: TDK; Polarized: N; CompType: Capacitor; Value: 0.1uF; U/M: EA; Cap_F: 0.0000001; Tolerance_%: 20; Value1: Unknown; VDC_V: 25; Value2: 25V; TaMin_C: -55; TaMax_C: 125; Cap_Case: 0402; SizeArea_mm2: 0.5; SizeAreaWB_mm2: 3; SizeX_mm: 1; SizeZ_mm: 0.6; AEC Category: Q200
C249 C250 C267 C268 = GCM188R71C105KA64D: CAP, CERM, 1 µF, 16 V, +/- 10%, X7R, AEC-Q200 Grade 1, 0603; Manufacturer: MuRata; Polarized: N; CompType: Capacitor; Value: 1uF; U/M: EA; Cap_F: 0.000001; Tolerance_%: 10; Value1: Unknown; VDC_V: 16; Value2: 16V; TaMin_C: -55; TaMax_C: 125; Cap_Case: 0603; SizeArea_mm2: 1.28; SizeAreaWB_mm2: 4.68; SizeX_mm: 1.6; SizeY_mm: 0.8; SizeZ_mm: 1; AEC Category: Q200; AEC Qualified: Y
C269 = GCM21BR71C475KA73L: CAP, CERM, 4.7 µF, 16 V, +/- 10%, X7R, AEC-Q200 Grade 1, 0805; Manufacturer: MuRata; Polarized: N; CompType: Capacitor; Value: 4.7uF; U/M: EA; Cap_F: 0.0000047; Tolerance_%: 10; Value1: Unknown; VDC_V: 16; Value2: 16V; TaMin_C: -55; TaMax_C: 125; Cap_Case: 0805; SizeArea_mm2: 2.5; SizeAreaWB_mm2: 6.75; SizeX_mm: 2; SizeY_mm: 1.25; SizeZ_mm: 1.45; AEC Category: Q200; AEC Qualified: Y; AEC Grade: 1
C270 = C0402C104K4RACAUTO: CAP, CERM, 0.1 µF, 16 V, +/- 10%, X7R, AEC-Q200 Grade 1, 0402; Manufacturer: Kemet; Polarized: N; CompType: Capacitor; Value: 0.1uF; U/M: EA; Cap_F: 0.0000001; Tolerance_%: 10; Value1: Unknown; VDC_V: 16; Value2: 16V; TaMin_C: -55; TaMax_C: 125; SizeArea_mm2: 0.5; SizeAreaWB_mm2: 3; SizeX_mm: 1; SizeZ_mm: 0.6; AEC Category: Q200; AEC Qualified: Y
C271 = 06035A221FAT2A: CAP, CERM, 220 pF, 50 V,+/- 1%, C0G/NP0, 0603; Manufacturer: AVX; Polarized: N; CompType: Capacitor; Value: 220pF; U/M: EA; Cap_F: 0.00000000022; Tolerance_%: 1; ESR_ohm: 0.083; Value1: 0.083 ohm; VDC_V: 50; Value2: 50V; TaMin_C: -55; TaMax_C: 125; SizeArea_mm2: 1.28; SizeAreaWB_mm2: 4.68; SizeX_mm: 1.6; SizeY_mm: 0.8; AEC Category: Q200; Green_Lifecycle: Active; Green_REACh: Passed
L2 L12-L14 = DFE252012PD-R47M: Inductor, Shielded, 470 nH, 4.7 A, 0.021 ohm, SMD; Manufacturer: MuRata Toko; Value: 470nH; Ind_H: 470.0E-9; Imax_A: 4.7; Irms: 4.7A @ 40C rise; Isat: 6.1A @ 30% inductance drop; DCR_ohm: 0.021; Value2: 4.7A; SizeAreaWB_mm2: 10.5; SizeArea_mm2: 5; SizeX_mm: 2.5; SizeY_mm: 2; SizeZ_mm: 1.2; AEC Category: Q200
R41 R91 R93 R145 = MCR01MRTF1002: RES, 10.0 k, 0.1%, 0.063 W, 0402; Manufacturer: Rohm; CompType: Resistor; Value: 10.0k; Res_ohm: 10000; Value_Code: 10k0; Tolerance_%: 0.1; Power_W: 0.063; Value2: 0.063W; VDC_V: 50; TempCo: 100 ppm/C; SizeArea_mm2: 0.5; SizeX_mm: 1; SizeZ_mm: 0.6; EIA_Code: E192; U/M: EA; AEC Category: Q200; AEC Qualified: N
R96 R97 = CRCW04020000Z0ED: RES, 0, 5%, 0.063 W, 0402; Manufacturer: Vishay-Dale; CompType: Resistor; Value: 0; Value_Code: 0000; Tolerance_%: 5; Power_W: 0.063; Value2: 0.063W; VDC_V: 50; TempCo: 200 ppm/C; SizeArea_mm2: 0.5; SizeX_mm: 1; SizeZ_mm: 0.6; EIA_Code: E24; U/M: EA; AEC Category: Q200
TP1 TP2 TP50-TP64 = PAD_1MM_SQUARE: as 3.3V on sheet DCDC PWR
U25 = LP87332DRHDRQ1: Dual High-Current Buck Converters And Dual Linear Regulators, RHD0028W (VQFN-28); Manufacturer: Texas Instruments; SymbolCreator: Altium; SizeArea_mm2: 25; SizeAreaWB_mm2: 49; SizeX_mm: 5; SizeZ_mm: 1; CompType: IC; U/M: EA
U26 = CMP-0013819-2: Dual High-Current Buck Converters And Dual Linear Regulators, RHD0028W (VQFN-28); Manufacturer: Texas Instruments; SizeX_mm: 5; CompType: IC; SizeZ_mm: 1; SizeArea_mm2: 25; SizeAreaWB_mm2: 49; U/M: EA
U27 = TPS22965QWDSGRQ1: 5.5V, 4A, 16mΩ Automotive Load Switch With Adjustable Rise Time and Optional Quick Output Discharge, DSG0008B (WSON-8); Manufacturer: Texas Instruments; SymbolCreator: a0411947; SizeArea_mm2: 4; SizeAreaWB_mm2: 9; SizeX_mm: 2; SizeZ_mm: 0.8; CompType: IC; U/M: EA

## Sheet ANA PWR.SchDoc: ANA PWR
size 558 x 431 mm; Date: Not shown in title block; ApprovedBy: Not shown in title block; CheckedBy: Not shown in title block; Author: Not shown in title block; CompanyName: Not shown in title block; DrawnBy: Donovan Porter; Engineer: Not shown in title block; Organization: Not shown in title block; Address1: Not shown in title block; Address2: Not shown in title block; Address3: Not shown in title block; Address4: Not shown in title block; DocumentNumber: 9; Revision: Use project parameter SCH_Rev; SheetNumber: 9; SheetTotal: 12; PageSetup: Record=PageOptions¦CenterHorizontal=True¦CenterVertical=True¦PrintScale=1.00¦XCorrection=1.00¦YCorrection=1.00¦PrintKind=0¦BorderSize=5000000¦LeftOffset=0¦BottomOffset=0¦Orientation=2¦PaperLength=1000¦PaperWidth=1000¦Scale=100¦PaperSource=15¦PrintQuality=600¦MediaType=1¦DitherType=10¦PaperKind=Letter¦PrintScaleMode=1
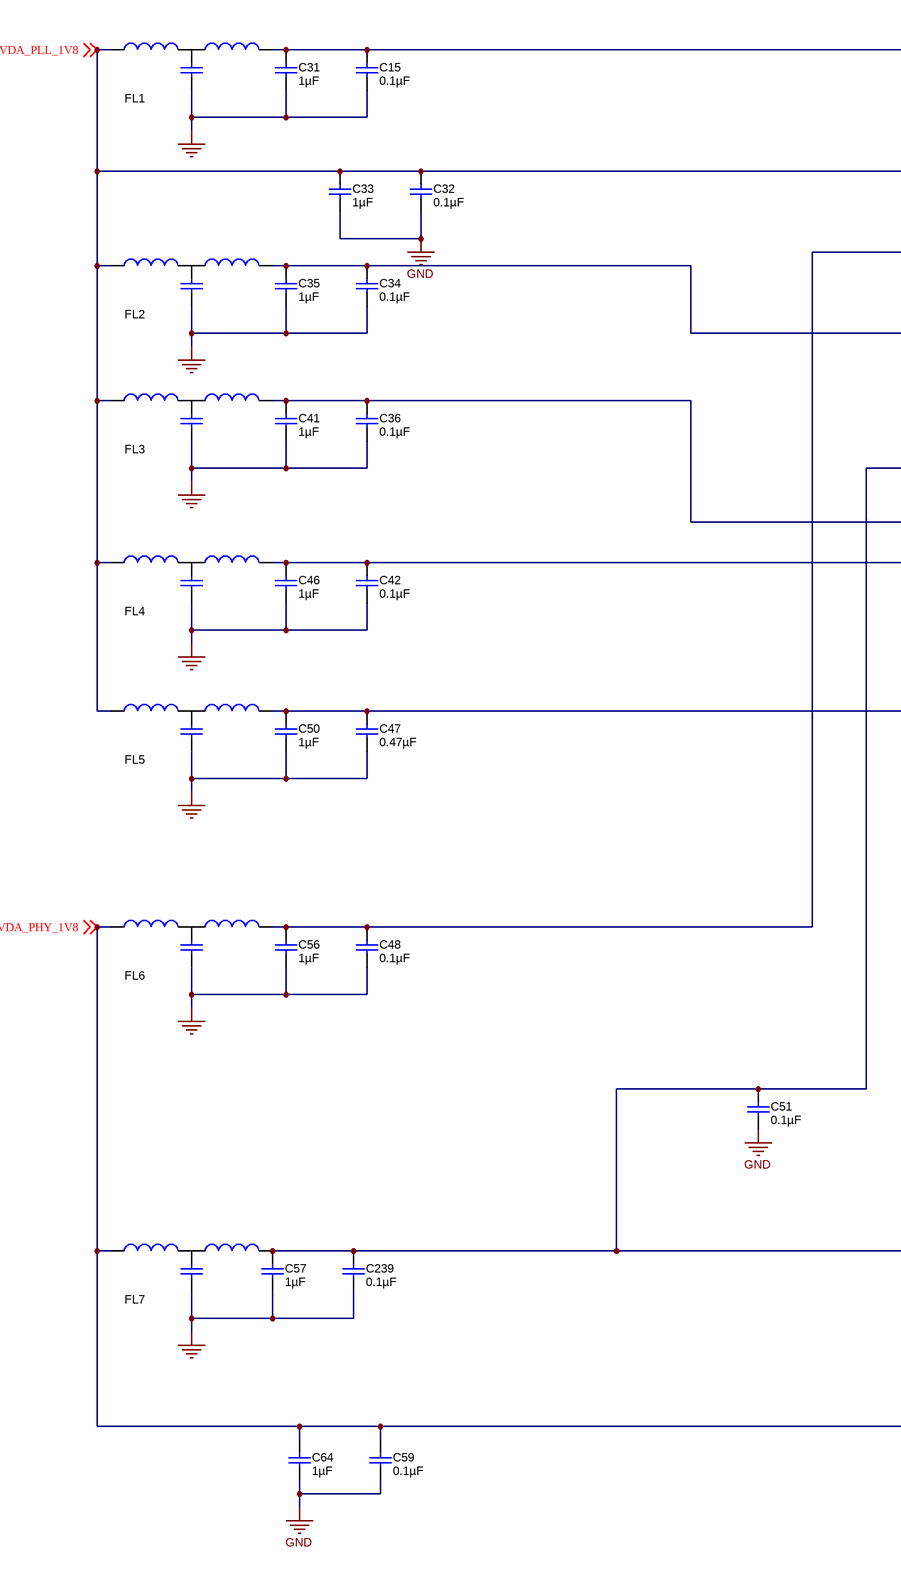
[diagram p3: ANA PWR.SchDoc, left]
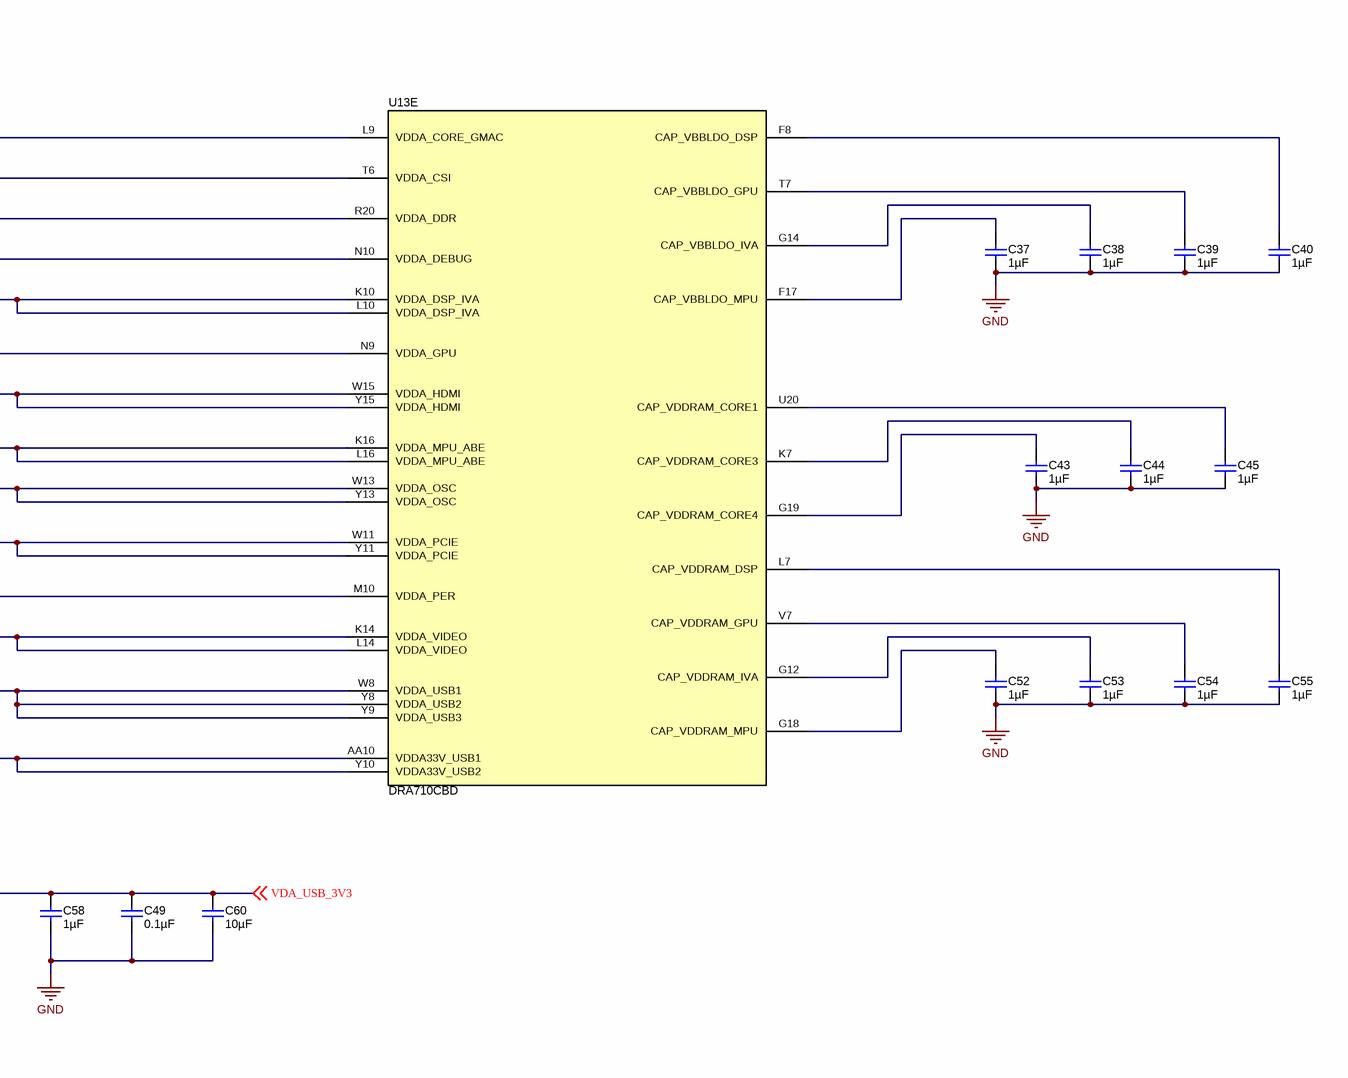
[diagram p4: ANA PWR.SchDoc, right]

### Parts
C15  ValueDisplayed: 0.1µF  [0402]  (hidden comment: GRM155R71C104KA88D)
C31  ValueDisplayed: 1µF  [0402_070]  (hidden comment: GCM155C71A105KE38D)
C32  ValueDisplayed: 0.1µF  [0402]  (hidden comment: GRM155R71C104KA88D)
C33  ValueDisplayed: 1µF  [0402_070]  (hidden comment: GCM155C71A105KE38D)
C34  ValueDisplayed: 0.1µF  [0402L]  (hidden comment: GRM155R71C104KA88D)
C35  ValueDisplayed: 1µF  [0402_070]  (hidden comment: GCM155C71A105KE38D)
C36  ValueDisplayed: 0.1µF  [0402L]  (hidden comment: GRM155R71C104KA88D)
C37  ValueDisplayed: 1µF  [0402_070]  (hidden comment: GCM155C71A105KE38D)
C38  ValueDisplayed: 1µF  [0402_070]  (hidden comment: GCM155C71A105KE38D)
C39  ValueDisplayed: 1µF  [0402_070]  (hidden comment: GCM155C71A105KE38D)
C40  ValueDisplayed: 1µF  [0402_070]  (hidden comment: GCM155C71A105KE38D)
C41  ValueDisplayed: 1µF  [0402_070]  (hidden comment: GCM155C71A105KE38D)
C42  ValueDisplayed: 0.1µF  [0402L]  (hidden comment: GRM155R71C104KA88D)
C43  ValueDisplayed: 1µF  [0402_070]  (hidden comment: GCM155C71A105KE38D)
C44  ValueDisplayed: 1µF  [0402_070]  (hidden comment: GCM155C71A105KE38D)
C45  ValueDisplayed: 1µF  [0402_070]  (hidden comment: GCM155C71A105KE38D)
C46  ValueDisplayed: 1µF  [0402_070]  (hidden comment: GCM155C71A105KE38D)
C47  ValueDisplayed: 0.47µF  [0402L]  (hidden comment: GCM155C71A474KE36D)
C48  ValueDisplayed: 0.1µF  [0402]  (hidden comment: GRM155R71C104KA88D)
C49  ValueDisplayed: 0.1µF  [0402]  (hidden comment: GRM155R71C104KA88D)
C50  ValueDisplayed: 1µF  [0402_070]  (hidden comment: GCM155C71A105KE38D)
C51  ValueDisplayed: 0.1µF  [0402L]  (hidden comment: GRM155R71C104KA88D)
C52  ValueDisplayed: 1µF  [0402_070]  (hidden comment: GCM155C71A105KE38D)
C53  ValueDisplayed: 1µF  [0402_070]  (hidden comment: GCM155C71A105KE38D)
C54  ValueDisplayed: 1µF  [0402_070]  (hidden comment: GCM155C71A105KE38D)
C55  ValueDisplayed: 1µF  [0402_070]  (hidden comment: GCM155C71A105KE38D)
C56  ValueDisplayed: 1µF  [0402_070]  (hidden comment: GCM155C71A105KE38D)
C57  ValueDisplayed: 1µF  [0402_070]  (hidden comment: GCM155C71A105KE38D)
C58  ValueDisplayed: 1µF  [0402_070]  (hidden comment: GCM155C71A105KE38D)
C59  ValueDisplayed: 0.1µF  [0402L]  (hidden comment: GRM155R71C104KA88D)
C60  ValueDisplayed: 10µF  [0805_HV]  (hidden comment: GCM21BR71A106KE22L)
C64  ValueDisplayed: 1µF  [0402_070]  (hidden comment: GCM155C71A105KE38D)
C239  ValueDisplayed: 0.1µF  [0402L]  (hidden comment: GRM155R71C104KA88D)
FL1  NFM21PC474R1C3D  [Murata_NFM21PC]  (value not drawn)
FL2  NFM21PC474R1C3D  [Murata_NFM21PC]  (value not drawn)
FL3  NFM21PC474R1C3D  [Murata_NFM21PC]  (value not drawn)
FL4  NFM21PC474R1C3D  [Murata_NFM21PC]  (value not drawn)
FL5  NFM21PC474R1C3D  [Murata_NFM21PC]  (value not drawn)
FL6  NFM21PC474R1C3D  [Murata_NFM21PC]  (value not drawn)
FL7  NFM21PC474R1C3D  [Murata_NFM21PC]  (value not drawn)
U13  DRA710CBD  [CBD0538A]  (part E of 5)

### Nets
GND: C15.2 C31.2 C32.2 C33.2 C34.2 C35.2 C36.2 C37.2 C38.2 C39.2 C40.2 C41.2 C42.2 C43.2 C44.2 C45.2 C46.2 C47.2 C48.2 C49.2 C50.2 C51.2 C52.2 C53.2 C54.2 C55.2 C56.2 C57.2 C58.2 C59.2 C60.2 C64.2 C239.2 FL1.2 FL2.2 FL3.2 FL4.2 FL5.2 FL6.2 FL7.2
VDA_PHY_1V8: C59.1 C64.1 FL6.1 FL7.1 U13.W8(VDDA_USB1) U13.Y8(VDDA_USB2) U13.Y9(VDDA_USB3) ; off-sheet VDA_PHY_1V8
VDA_PLL_1V8: C32.1 C33.1 FL1.1 FL2.1 FL3.1 FL4.1 FL5.1 U13.R20(VDDA_DDR) ; off-sheet VDA_PLL_1V8
VDA_USB_3V3: C49.1 C58.1 C60.1 U13.AA10(VDDA33V_USB1) U13.Y10(VDDA33V_USB2) ; off-sheet VDA_USB_3V3
NetC15_1: C15.1 C31.1 FL1.3 U13.K10(VDDA_DSP_IVA) U13.L9(VDDA_CORE_GMAC) U13.L10(VDDA_DSP_IVA)
NetC34_1: C34.1 C35.1 FL2.3 U13.M10(VDDA_PER) U13.N9(VDDA_GPU) U13.N10(VDDA_DEBUG)
NetC36_1: C36.1 C41.1 FL3.3 U13.K16(VDDA_MPU_ABE) U13.L16(VDDA_MPU_ABE)
NetC37_1: C37.1 U13.F17(CAP_VBBLDO_MPU)
NetC38_1: C38.1 U13.G14(CAP_VBBLDO_IVA)
NetC39_1: C39.1 U13.T7(CAP_VBBLDO_GPU)
NetC40_1: C40.1 U13.F8(CAP_VBBLDO_DSP)
NetC42_1: C42.1 C46.1 FL4.3 U13.W13(VDDA_OSC) U13.Y13(VDDA_OSC)
NetC43_1: C43.1 U13.G19(CAP_VDDRAM_CORE4)
NetC44_1: C44.1 U13.K7(CAP_VDDRAM_CORE3)
NetC45_1: C45.1 U13.U20(CAP_VDDRAM_CORE1)
NetC47_1: C47.1 C50.1 FL5.3 U13.K14(VDDA_VIDEO) U13.L14(VDDA_VIDEO)
NetC48_1: C48.1 C56.1 FL6.3 U13.T6(VDDA_CSI)
NetC51_1: C51.1 C57.1 C239.1 FL7.3 U13.W11(VDDA_PCIE) U13.W15(VDDA_HDMI) U13.Y11(VDDA_PCIE) U13.Y15(VDDA_HDMI)
NetC52_1: C52.1 U13.G18(CAP_VDDRAM_MPU)
NetC53_1: C53.1 U13.G12(CAP_VDDRAM_IVA)
NetC54_1: C54.1 U13.V7(CAP_VDDRAM_GPU)
NetC55_1: C55.1 U13.L7(CAP_VDDRAM_DSP)

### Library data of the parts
C15 C32 C48 C49 = GRM155R71C104KA88D: CAP, CERM, 0.1 µF, 16 V, +/- 10%, X7R, 0402; Manufacturer: MuRata; Polarized: N; CompType: Capacitor; Value: 0.1uF; U/M: EA; Cap_F: 0.0000001; Tolerance_%: 10; Value1: Unknown; VDC_V: 16; Value2: 16V; TaMin_C: -55; TaMax_C: 125; SizeArea_mm2: 0.5; SizeAreaWB_mm2: 3; SizeX_mm: 1; SizeZ_mm: 0.6; AEC Category: Q200
C31 C33 C35 C37-C41 C43-C46 C50 C52-C58 C64 = GCM155C71A105KE38D: CAP, CERM, 1 µF, 10 V, +/- 10%, X7S, AEC-Q200 Grade 1, 0402; Manufacturer: MuRata; Polarized: N; CompType: Capacitor; Value: 1uF; U/M: EA; Cap_F: 0.000001; Tolerance_%: 10; Value1: Unknown; Value2: 10V; TaMin_C: -55; TaMax_C: 125; Cap_Case: 0402; SizeArea_mm2: 0.5; SizeAreaWB_mm2: 3; SizeX_mm: 1; SizeZ_mm: 0.7; AEC Category: Q200; AEC Qualified: Y
C34 C36 C42 C51 C59 C239 = GRM155R71C104KA88D: CAP, CERM, 0.1 µF, 16 V, +/- 10%, X7R, 0402; Manufacturer: MuRata; Polarized: N; CompType: Capacitor; Value: 0.1uF; U/M: EA; Cap_F: 0.0000001; Tolerance_%: 10; Value1: Unknown; VDC_V: 16; Value2: 16V; TaMin_C: -55; TaMax_C: 125; Cap_Case: 0402; SizeArea_mm2: 0.5; SizeAreaWB_mm2: 3; SizeX_mm: 1; SizeZ_mm: 0.6; AEC Category: Q200
C47 = GCM155C71A474KE36D: CAP, CERM, 0.47 µF, 10 V, +/- 10%, X7S, 0402; Manufacturer: MuRata; Polarized: N; CompType: Capacitor; Value: 0.47uF; U/M: EA; Cap_F: 0.00000047; Tolerance_%: 10; Value1: Unknown; Value2: 10V; TaMin_C: -55; TaMax_C: 125; Cap_Case: 0402; SizeArea_mm2: 0.5; SizeAreaWB_mm2: 3; SizeX_mm: 1; SizeZ_mm: 0.6; AEC Category: Q200
C60 = GCM21BR71A106KE22L: as C230 on sheet LP873x (PMIC)
FL1-FL7 = NFM21PC474R1C3D: Chip EMIFIL Chip 3-Terminal Capacitor for Large Current for General; Manufacturer: MuRata; CompType: Filter; Value: 0.47uF; SizeAreaWB_mm2: 6.75; SizeArea_mm2: 2.5; SizeX_mm: 2; SizeY_mm: 1.25; SizeZ_mm: 0.95
U13 = DRA710CBD: Infotainment Applications Processor, CBD0538A (BGA-538); Manufacturer: Texas Instruments; SymbolCreator: Altium; SizeArea_mm2: 289; SizeAreaWB_mm2: 361; SizeX_mm: 17; SizeZ_mm: 1.298; CompType: IC; U/M: EA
